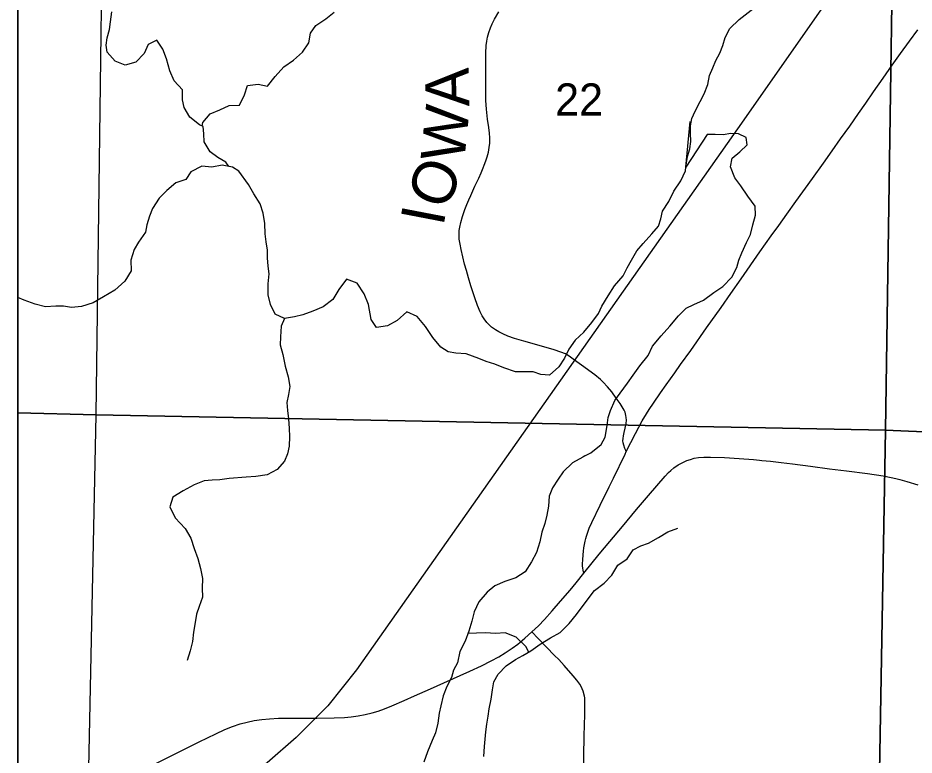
# Model space of a CAD drawing. Extents: x 0 to 34, y 0 to 22.
# Drawn here: x 1.631 to 2.794, y 17.774 to 18.731 of the extents above; entities that cross this region are included whole.
import ezdxf

# ---------------------------------------------------------------- set-up
doc = ezdxf.new("R2010")
doc.units = 0
for name, color, linetype in [('GM_X_Corporation', 7, 'Continuous'), ('GM_X_Minor_River', 7, 'Continuous'), ('GM_X_Rail_Line', 7, 'Continuous'), ('GM_X_Section_Text', 7, 'Continuous'), ('GM_X_State_Route', 7, 'Continuous'), ('GM_X_Township_Road', 7, 'Continuous'), ('GM_X_Township_Road_Text', 7, 'Continuous'), ('SH_Text', 7, 'Continuous')]:
    doc.layers.add(name, color=color, linetype=linetype)

msp = doc.modelspace()

# ---------------------------------------------------------------- linework, layer by layer
at = {"layer": 'GM_X_Corporation'}
for points in [[(8.4311, 21.3734), (1.6311, 21.3734), (1.6311, 16.1731), (2.3716, 16.1532), (2.3935, 16.1523), (3.7652, 16.1115), (4.1576, 16.1007)], [(4.7823, 18.128), (4.0508, 18.1454), (3.7812, 18.1547), (3.7776, 18.3354), (3.7807, 18.4204), (3.7875, 18.9248), (3.7889, 19.1658), (3.7877, 19.187), (3.1142, 19.2057), (2.7749, 19.2162), (2.7798, 20.0198), (2.7831, 20.242), (2.7976, 21.3075), (2.7987, 21.3734), (1.6311, 21.3734), (1.6311, 16.1731), (2.3716, 16.1532), (2.3935, 16.1523), (3.7652, 16.1115), (4.1576, 16.1007)], [(1.8974, 17.1907), (1.7115, 17.1949), (1.7326, 18.216), (2.7572, 18.1961), (2.7424, 17.3579)], [(2.7424, 17.3579), (2.7572, 18.1961), (3.7781, 18.1522), (3.763, 17.3579)]]:
    msp.add_lwpolyline(points, dxfattribs=at)
for points in [[(1.6311, 19.242), (1.6311, 18.2188), (1.7326, 18.216), (1.7459, 19.2387)], [(1.7459, 19.2387), (2.7721, 19.2162), (2.7572, 18.1961), (1.7326, 18.216)], [(3.7879, 19.187), (3.7781, 18.1522), (2.7572, 18.1961), (2.7721, 19.2162)], [(1.6311, 18.2188), (1.6311, 17.1972), (1.7115, 17.1949), (1.7326, 18.216)]]:
    msp.add_lwpolyline(points, close=True, dxfattribs=at)
at = {"layer": 'GM_X_Minor_River'}
for points in [[(1.8716, 18.5905), (1.8667, 18.5927), (1.8541, 18.6025), (1.8468, 18.615), (1.8448, 18.6252), (1.8447, 18.6381), (1.834, 18.6498), (1.8283, 18.6627), (1.824, 18.6782), (1.8194, 18.6911), (1.8113, 18.7024), (1.8, 18.697), (1.7948, 18.6852), (1.7842, 18.6741), (1.7702, 18.6702), (1.7573, 18.6755), (1.747, 18.6868), (1.7458, 18.6963), (1.7468, 18.7058), (1.7498, 18.7164), (1.7513, 18.7263), (1.7531, 18.7392)], [(1.8704, 18.591), (1.8712, 18.5958), (1.8806, 18.6068), (1.8931, 18.6122), (1.9052, 18.6176), (1.9188, 18.6181), (1.9252, 18.6314), (1.9292, 18.6436), (1.9429, 18.6456), (1.955, 18.643), (1.9648, 18.6552), (1.9761, 18.6678), (1.9889, 18.6767), (2.0006, 18.687), (2.0089, 18.6992), (2.011, 18.7117), (2.0178, 18.7216), (2.0306, 18.7301), (2.0416, 18.7389)], [(2.4979, 18.5377), (2.5, 18.5514), (2.5033, 18.5616), (2.5043, 18.5711), (2.5039, 18.5817), (2.5042, 18.5912), (2.5056, 18.601), (2.51, 18.6106), (2.5167, 18.6231), (2.5219, 18.633), (2.5264, 18.6452), (2.5285, 18.6566), (2.533, 18.6665), (2.5371, 18.6764), (2.5419, 18.6859), (2.546, 18.6958), (2.5489, 18.7061), (2.5552, 18.7179), (2.5672, 18.7294), (2.5867, 18.7447)], [(1.9048, 18.5385), (1.9011, 18.544), (1.8908, 18.5504), (1.8805, 18.5575), (1.8729, 18.5707), (1.8724, 18.581), (1.8716, 18.5905)], [(2.5559, 18.5383), (2.5582, 18.5493), (2.568, 18.5574), (2.5777, 18.5666), (2.5765, 18.5764), (2.5662, 18.5808), (2.5564, 18.5815), (2.5466, 18.5795), (2.536, 18.5801), (2.5258, 18.58), (2.4979, 18.5377), (2.5037, 18.5969), (2.5045, 18.5957)], [(1.9178, 18.5323), (1.9095, 18.5376), (1.8962, 18.5401), (1.8826, 18.5378), (1.8697, 18.5392), (1.8554, 18.5317)], [(1.8554, 18.5317), (1.849, 18.5215), (1.8362, 18.5172), (1.8242, 18.5072), (1.8145, 18.4976), (1.8059, 18.4839), (1.8018, 18.4743), (1.7986, 18.4629), (1.7968, 18.4534), (1.7878, 18.4405), (1.7819, 18.4309), (1.7775, 18.4168), (1.778, 18.4032), (1.7698, 18.3898), (1.7567, 18.378), (1.742, 18.3695), (1.7288, 18.3617), (1.7137, 18.3567), (1.7005, 18.3554), (1.6903, 18.3572), (1.6804, 18.3571), (1.6668, 18.3565), (1.6535, 18.3598), (1.6391, 18.365), (1.6311, 18.3687)], [(2.3651, 18.3229), (2.3655, 18.3233), (2.3542, 18.3133), (2.346, 18.3015), (2.3404, 18.2897), (2.333, 18.2786), (2.321, 18.2675), (2.3096, 18.2685), (2.2997, 18.2718), (2.2884, 18.2721), (2.2767, 18.272), (2.2618, 18.2771), (2.2501, 18.2819), (2.2387, 18.2852), (2.2292, 18.2893), (2.2128, 18.2952), (2.1996, 18.2962), (2.1897, 18.298), (2.1798, 18.3039), (2.1698, 18.3167), (2.1599, 18.331), (2.1491, 18.3438), (2.1358, 18.3497), (2.1234, 18.3386), (2.1106, 18.3316), (2.0967, 18.3296), (2.0894, 18.3398), (2.0861, 18.3594), (2.0803, 18.3734), (2.0715, 18.3869), (2.0574, 18.3921), (2.0477, 18.3791), (2.0399, 18.3658), (2.0275, 18.3562), (2.0139, 18.3507), (2.0007, 18.346), (1.9902, 18.3436), (1.9773, 18.3412), (1.9648, 18.3468), (1.959, 18.3592), (1.9558, 18.3721), (1.956, 18.3861), (1.957, 18.3994), (1.9558, 18.4092), (1.9549, 18.4198), (1.9552, 18.4301), (1.9532, 18.4407), (1.952, 18.4513), (1.9518, 18.4645), (1.9494, 18.4778), (1.9455, 18.4902), (1.9374, 18.5031), (1.9305, 18.5151), (1.9178, 18.5323)], [(2.3655, 18.3233), (2.3762, 18.336), (2.3848, 18.3479), (2.3889, 18.3574), (2.3971, 18.3707), (2.4054, 18.3837), (2.4167, 18.3967), (2.4219, 18.407), (2.4275, 18.4169), (2.4343, 18.4291), (2.4425, 18.4386), (2.4538, 18.4513), (2.4625, 18.4612), (2.4654, 18.4707), (2.4676, 18.4806), (2.4759, 18.4932), (2.4822, 18.5065), (2.4916, 18.5199), (2.4976, 18.5328), (2.4979, 18.5377)], [(2.3667, 18.163), (2.3747, 18.1668), (2.3879, 18.1775), (2.3931, 18.187), (2.3957, 18.2022), (2.3971, 18.2125), (2.4001, 18.222), (2.4057, 18.2346), (2.4128, 18.2445), (2.4222, 18.2571), (2.4297, 18.2678), (2.4384, 18.2796), (2.4489, 18.293), (2.4549, 18.3055), (2.4661, 18.3189), (2.4774, 18.3315), (2.4883, 18.3445), (2.4985, 18.3545), (2.5083, 18.3595), (2.5208, 18.3649), (2.5343, 18.3749), (2.546, 18.3829), (2.5577, 18.3948), (2.5641, 18.4074), (2.5666, 18.4169), (2.5707, 18.4264), (2.5767, 18.4397), (2.582, 18.4504), (2.5849, 18.4629), (2.5886, 18.4755), (2.5878, 18.4872), (2.5786, 18.5001), (2.5694, 18.5133), (2.5617, 18.5238), (2.5559, 18.5383)], [(1.9773, 18.3413), (1.9729, 18.3313), (1.9719, 18.3173), (1.9716, 18.3071), (1.9748, 18.2946), (1.978, 18.2794), (1.9819, 18.2655), (1.9839, 18.253), (1.9825, 18.2427), (1.9803, 18.2321), (1.9808, 18.2219), (1.9821, 18.2109), (1.9833, 18.1984), (1.9838, 18.1882), (1.9832, 18.1756), (1.981, 18.1654), (1.977, 18.1559), (1.9676, 18.1452), (1.9544, 18.1382), (1.9401, 18.1361), (1.9272, 18.1352), (1.9053, 18.1335), (1.8932, 18.1319), (1.8833, 18.1314), (1.8728, 18.1305), (1.8599, 18.1254), (1.8456, 18.1177), (1.8321, 18.1092), (1.8281, 18.0967), (1.835, 18.0823), (1.848, 18.0688), (1.8557, 18.056), (1.8597, 18.0428), (1.8647, 18.0296), (1.8682, 18.0167), (1.8707, 18.0039), (1.8704, 17.991), (1.8705, 17.9796), (1.8665, 17.9674), (1.8628, 17.9572), (1.861, 17.9465), (1.8589, 17.934), (1.8575, 17.9219), (1.8546, 17.9097), (1.8509, 17.8972)], [(2.3667, 18.163), (2.3645, 18.1611), (2.3509, 18.1537), (2.3389, 18.1422), (2.3322, 18.1327), (2.3248, 18.1212), (2.3207, 18.1106), (2.3197, 18.0977), (2.3176, 18.0859), (2.315, 18.0753), (2.311, 18.0638), (2.3085, 18.0513), (2.3041, 18.0376), (2.2977, 18.0254), (2.2895, 18.0124), (2.2775, 18.0047), (2.2632, 17.9997), (2.25, 17.9942), (2.2402, 17.9858), (2.2294, 17.9735), (2.2231, 17.9606), (2.2202, 17.9484), (2.2162, 17.9355), (2.2114, 17.9222), (2.2047, 17.9088), (2.2018, 17.8944), (2.1966, 17.8849), (2.1937, 17.8753), (2.1878, 17.8635), (2.183, 17.8514), (2.1801, 17.8384), (2.1779, 17.8289), (2.1761, 17.816), (2.1729, 17.8035), (2.1688, 17.7932), (2.1625, 17.7787), (2.1581, 17.7654)], [(2.3685, 17.9738), (2.3794, 17.9881), (2.3918, 17.9977), (2.402, 18.008), (2.4099, 18.021), (2.422, 18.0294), (2.4295, 18.0409), (2.4396, 18.0459), (2.4495, 18.0494), (2.4623, 18.0571), (2.4748, 18.0644), (2.4876, 18.069)], [(2.236, 17.7727), (2.2366, 17.7856), (2.2377, 17.7951), (2.2383, 17.8046), (2.2397, 17.8144), (2.2415, 17.8251), (2.2429, 17.8345), (2.2455, 17.8471), (2.2472, 17.8592), (2.249, 17.8695), (2.2546, 17.8794), (2.2647, 17.8905), (2.2767, 17.8986), (2.2865, 17.9036), (2.297, 17.9098), (2.3091, 17.9186), (2.3222, 17.9267), (2.335, 17.9337), (2.3466, 17.9452), (2.356, 17.957), (2.3685, 17.9738)], [(2.2941, 17.9081), (2.2902, 17.9154), (2.2776, 17.9274), (2.2635, 17.9333), (2.251, 17.9321), (2.2381, 17.9331), (2.2147, 17.9321)]]:
    msp.add_lwpolyline(points, dxfattribs=at)
at = {"layer": 'GM_X_Rail_Line'}
msp.add_lwpolyline([(4.1788, 20.304), (4.0429, 20.1945), (3.3384, 19.6119), (3.2847, 19.5633), (3.2446, 19.5253), (3.2015, 19.4768), (3.1607, 19.4315), (3.1275, 19.3905), (3.0936, 19.3436), (2.5732, 18.599), (2.0707, 17.885), (2.0334, 17.8382), (1.9924, 17.7972), (1.9547, 17.7644), (1.7027, 17.5707), (1.6311, 17.5139)], dxfattribs=at)
at = {"layer": 'GM_X_State_Route'}
msp.add_line((2.2983, 17.9343), (2.3025, 17.9383), dxfattribs=at)
for points in [[(2.4206, 18.1685), (2.4266, 18.1803), (2.4326, 18.1919), (2.4415, 18.2082), (2.4468, 18.2173), (2.4504, 18.223), (2.4559, 18.2313), (2.465, 18.2446), (2.4725, 18.2552), (2.4835, 18.2709), (2.4911, 18.2814), (2.5043, 18.2995), (2.525, 18.329), (2.5437, 18.3554), (2.5566, 18.3737), (2.5696, 18.3926), (2.5942, 18.4277), (2.6089, 18.4485), (2.6187, 18.4621), (2.6292, 18.4768), (2.6408, 18.493), (2.6625, 18.5232), (2.6767, 18.5429), (2.6877, 18.5587), (2.6988, 18.5744), (2.7107, 18.5911), (2.7222, 18.6073), (2.7314, 18.6206), (2.7417, 18.6354), (2.754, 18.6533), (2.7658, 18.67), (2.7767, 18.6852), (2.7882, 18.7014), (2.7989, 18.7159)], [(2.3657, 18.0106), (2.3648, 18.0146), (2.3644, 18.0169), (2.364, 18.0203), (2.364, 18.0228), (2.3642, 18.0278), (2.3646, 18.0345), (2.3652, 18.0393), (2.3658, 18.0437), (2.3665, 18.0479), (2.3673, 18.0522), (2.3681, 18.0556), (2.369, 18.0587), (2.3698, 18.0614), (2.3707, 18.064), (2.3726, 18.0692), (2.3758, 18.0766), (2.3867, 18.0989), (2.3984, 18.1229), (2.4039, 18.134), (2.4191, 18.1653), (2.4206, 18.1685)], [(2.3657, 18.0106), (2.3854, 18.0352), (2.3993, 18.0519), (2.4156, 18.0714), (2.4341, 18.0931), (2.4496, 18.1116), (2.471, 18.1365), (2.4753, 18.1411), (2.4785, 18.1441), (2.4823, 18.1474), (2.4881, 18.1511), (2.4942, 18.1544), (2.4993, 18.1567), (2.5041, 18.1584), (2.5089, 18.1597), (2.5145, 18.1607), (2.5213, 18.1613), (2.5301, 18.1614), (2.548, 18.1606), (2.5672, 18.1594), (2.5857, 18.158), (2.5937, 18.1572), (2.5968, 18.1569), (2.6079, 18.156), (2.6215, 18.1545), (2.6363, 18.1526), (2.6597, 18.1494), (2.6844, 18.1462), (2.7065, 18.1435), (2.7337, 18.1401), (2.754, 18.1369), (2.7644, 18.1349), (2.7705, 18.1336), (2.7759, 18.1322), (2.7849, 18.1296), (2.7991, 18.1251)], [(2.3025, 17.9383), (2.3067, 17.9424), (2.3145, 17.9505), (2.3244, 17.9615), (2.3355, 17.9741), (2.348, 17.9885), (2.3558, 17.9981), (2.3657, 18.0106)], [(1.7894, 17.7531), (1.8665, 17.7918), (1.8878, 17.8022), (1.8997, 17.8076), (1.9095, 17.8116), (1.9196, 17.8149), (1.9286, 17.8173), (1.9378, 17.8193), (1.9477, 17.8208), (1.9576, 17.8217), (1.9695, 17.8224), (1.9875, 17.8225), (2.0192, 17.8224), (2.0415, 17.8227), (2.0551, 17.8232), (2.0637, 17.824), (2.0729, 17.8253), (2.082, 17.827), (2.091, 17.8293), (2.0987, 17.8316), (2.1068, 17.8344), (2.1166, 17.8383), (2.1324, 17.8453), (2.146, 17.8514), (2.1665, 17.8604), (2.1841, 17.8682), (2.2176, 17.8832), (2.2327, 17.8903), (2.2454, 17.8968), (2.2552, 17.9021), (2.2637, 17.9072), (2.2724, 17.9131), (2.2798, 17.9186), (2.289, 17.9261), (2.2983, 17.9343)]]:
    msp.add_lwpolyline(points, dxfattribs=at)
at = {"layer": 'GM_X_Township_Road'}
msp.add_line((2.2983, 17.9343), (2.3025, 17.9383), dxfattribs=at)
for points in [[(2.4206, 18.1685), (2.42, 18.17), (2.419, 18.1724), (2.4174, 18.1766), (2.4167, 18.1799), (2.4164, 18.1824), (2.4165, 18.1854), (2.4172, 18.1891), (2.4181, 18.1933), (2.4194, 18.1988), (2.4205, 18.2049), (2.4208, 18.2092), (2.4206, 18.2129), (2.4202, 18.2154), (2.4191, 18.2196), (2.4179, 18.2224), (2.4155, 18.2267), (2.4141, 18.2288), (2.4128, 18.2309), (2.4103, 18.2345), (2.4077, 18.238), (2.4018, 18.246), (2.3963, 18.2527), (2.3908, 18.2586), (2.3872, 18.2621), (2.38, 18.268), (2.3721, 18.2738), (2.3655, 18.2785), (2.3535, 18.2873), (2.3464, 18.2923), (2.3416, 18.2952), (2.3359, 18.2976), (2.3271, 18.3006), (2.3199, 18.3027), (2.2876, 18.3119), (2.2757, 18.3154), (2.2669, 18.3185), (2.2606, 18.3212), (2.2551, 18.324), (2.2508, 18.3265), (2.2458, 18.3302), (2.243, 18.3326), (2.2396, 18.3362), (2.2362, 18.3407), (2.2336, 18.3449), (2.2311, 18.3499), (2.2278, 18.358), (2.2242, 18.3679), (2.219, 18.3838), (2.2159, 18.3939), (2.2132, 18.4035), (2.2109, 18.4118), (2.2086, 18.4214), (2.2062, 18.431), (2.2049, 18.4376), (2.204, 18.4443), (2.2037, 18.4499), (2.204, 18.4554), (2.2046, 18.4597), (2.2058, 18.4657), (2.208, 18.4735), (2.2112, 18.4829), (2.2136, 18.4892), (2.2163, 18.4955), (2.2189, 18.5011), (2.2243, 18.5129), (2.2292, 18.5236), (2.2322, 18.5304), (2.2349, 18.5367), (2.2362, 18.5402), (2.2384, 18.546), (2.2401, 18.5513), (2.2417, 18.5573), (2.2429, 18.5634), (2.2435, 18.5689), (2.2436, 18.5757), (2.2433, 18.5819), (2.2423, 18.5893), (2.2407, 18.6002), (2.2391, 18.6132), (2.2385, 18.6241), (2.2383, 18.6856), (2.2388, 18.6956), (2.2395, 18.7011), (2.2406, 18.7066), (2.2423, 18.7126), (2.2443, 18.7184), (2.2465, 18.7236), (2.2496, 18.7297), (2.2552, 18.7394)], [(2.3657, 18.0106), (2.3648, 18.0146), (2.3644, 18.0169), (2.364, 18.0203), (2.364, 18.0228), (2.3642, 18.0278), (2.3646, 18.0345), (2.3652, 18.0393), (2.3658, 18.0437), (2.3665, 18.0479), (2.3673, 18.0522), (2.3681, 18.0556), (2.369, 18.0587), (2.3698, 18.0614), (2.3707, 18.064), (2.3726, 18.0692), (2.3758, 18.0766), (2.3867, 18.0989), (2.3984, 18.1229), (2.4039, 18.134), (2.4191, 18.1653), (2.4206, 18.1685)], [(2.3025, 17.9383), (2.3067, 17.9424), (2.3145, 17.9505), (2.3244, 17.9615), (2.3355, 17.9741), (2.348, 17.9885), (2.3558, 17.9981), (2.3657, 18.0106)], [(2.3656, 17.7567), (2.3658, 17.7747), (2.3659, 17.7977), (2.3663, 17.8151), (2.3667, 17.8256), (2.3669, 17.8313), (2.3671, 17.8418), (2.3667, 17.8486), (2.3663, 17.8511), (2.3646, 17.8576), (2.362, 17.8633), (2.3602, 17.8665), (2.3566, 17.8716), (2.3519, 17.8774), (2.3399, 17.8908), (2.333, 17.8987), (2.3276, 17.9039), (2.3063, 17.9259), (2.2983, 17.9343)]]:
    msp.add_lwpolyline(points, dxfattribs=at)
at = {"layer": 'SH_Text'}
msp.add_line((1.6311, 14.5734), (1.6311, 21.3734), dxfattribs=at)

# ---------------------------------------------------------------- texts
at = {"layer": 'GM_X_Section_Text'}
msp.add_text('22', height=0.04186, rotation=0, dxfattribs=at).set_placement((2.3283, 18.6046))
at = {"layer": 'GM_X_Township_Road_Text'}
for s, rotation, p in [('A', 91.4742, (2.2172, 18.6167)), ('W', 84.1385, (2.2102, 18.5433)), ('O', 67.5438, (2.1867, 18.4798)), ('I', 79.0996, (2.1831, 18.4597))]:
    msp.add_text(s, height=0.0568, rotation=rotation, dxfattribs=at).set_placement(p)

doc.saveas('drawing.dxf')
